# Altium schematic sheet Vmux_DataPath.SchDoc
size A3; DocumentNumber: 3; SheetNumber: 3; SheetTotal: 5
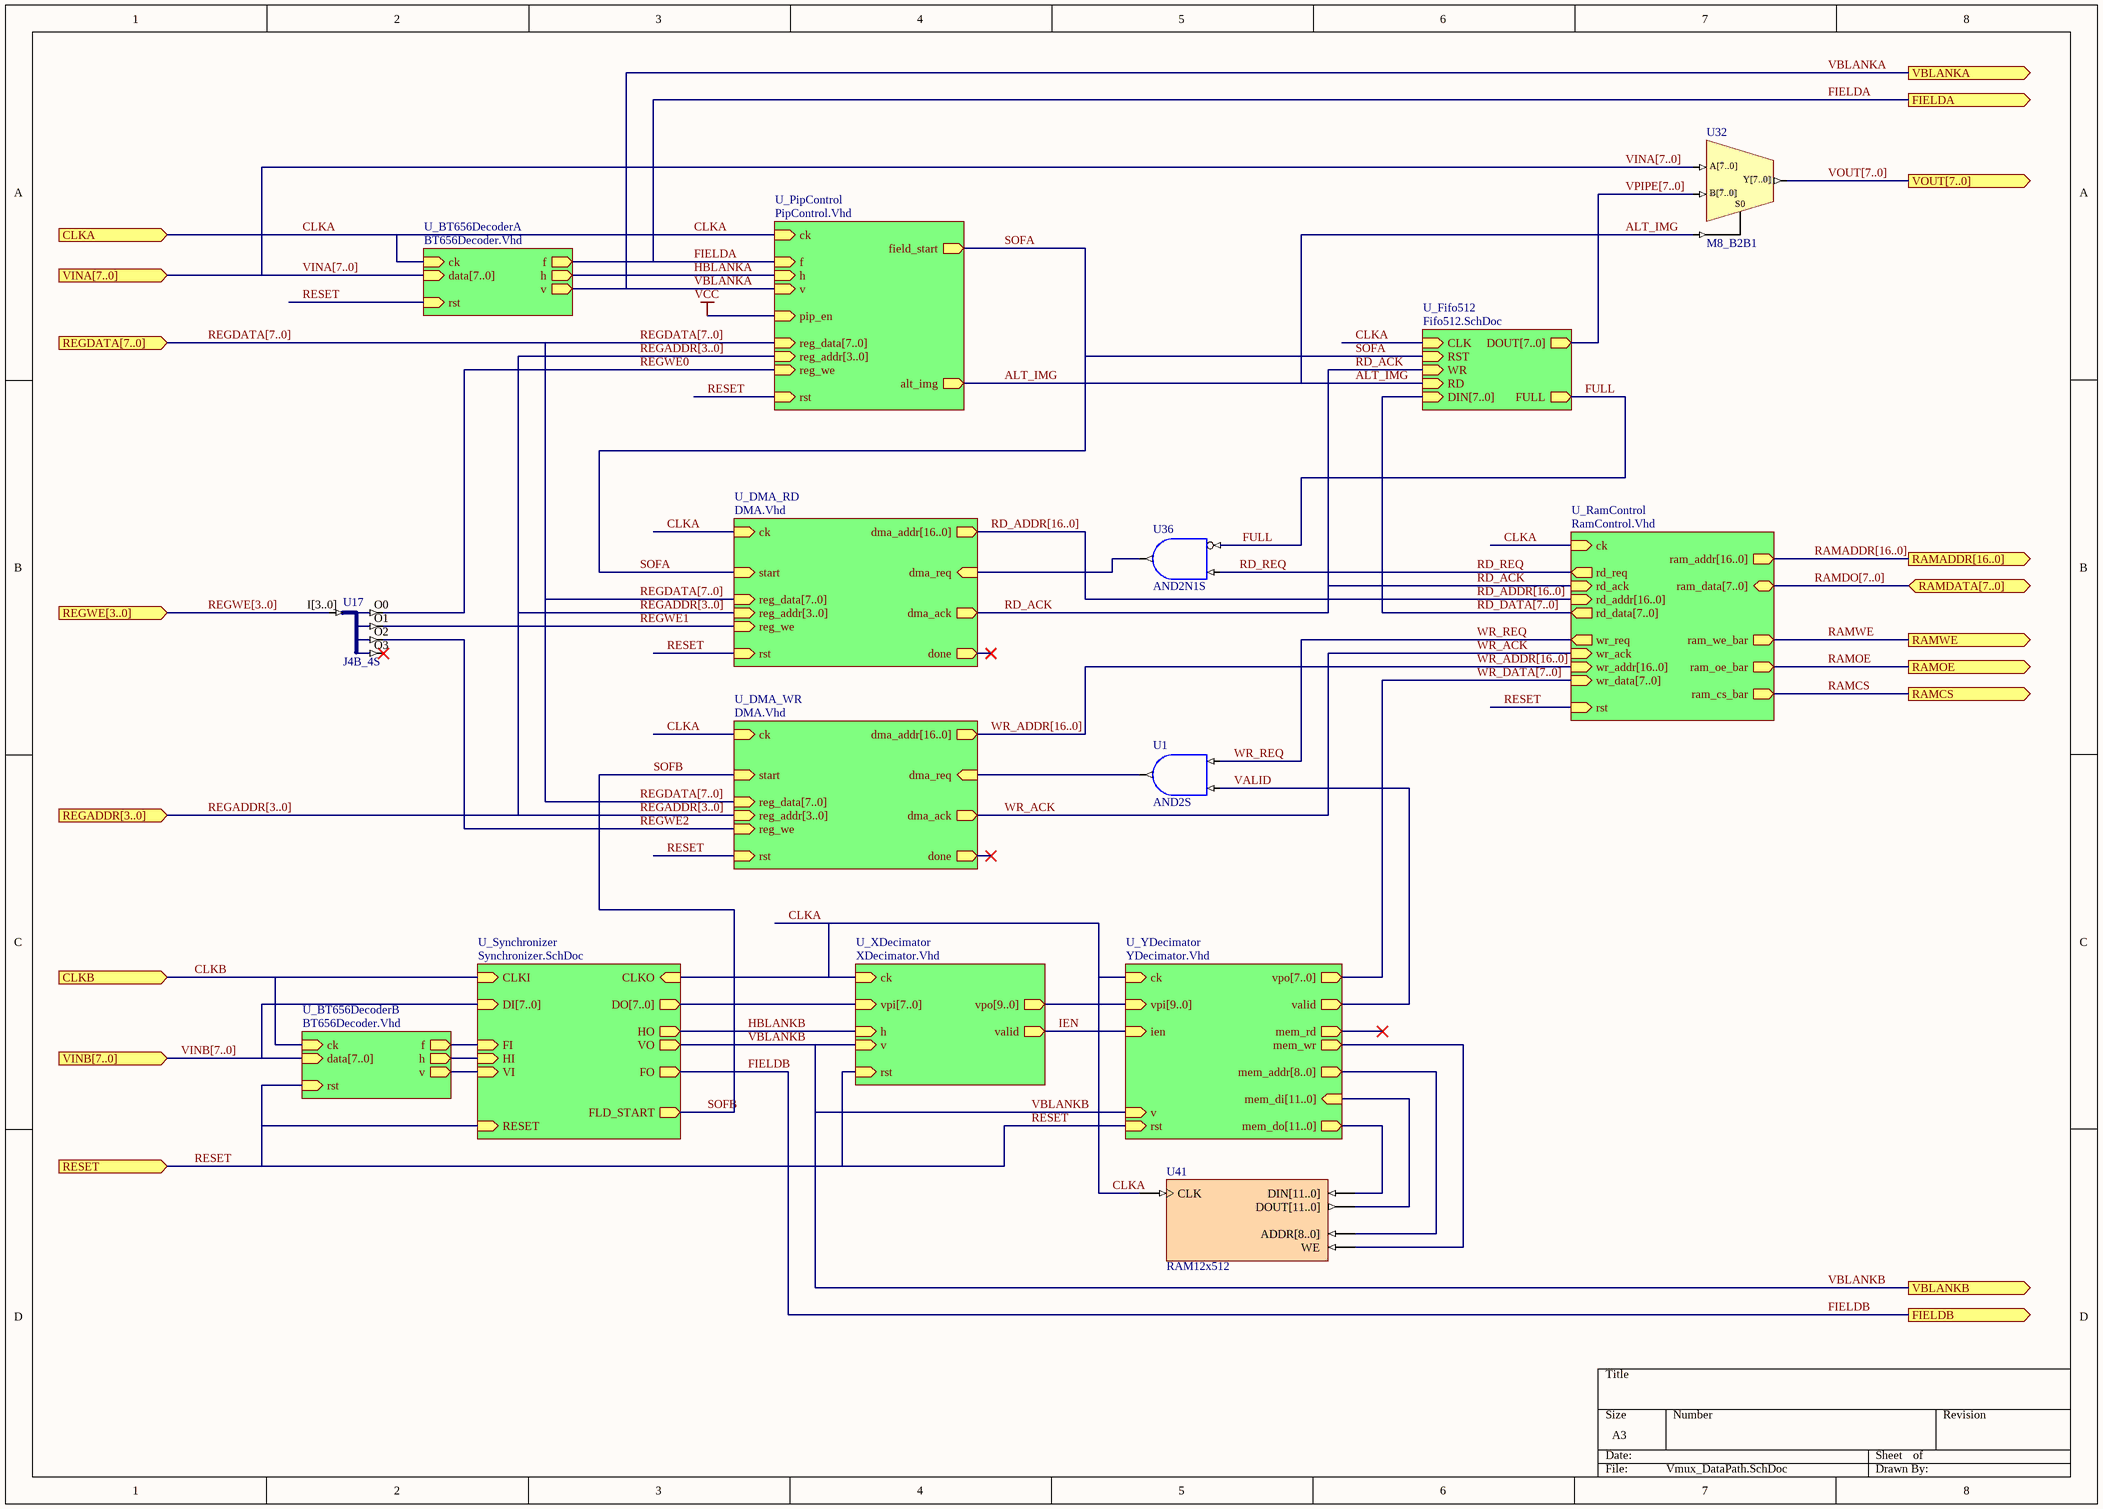
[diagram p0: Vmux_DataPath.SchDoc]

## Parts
U1  AND2S
U17  J4B_4S
U32  M8_B2B1
U36  AND2N1S
U41  RAM12x512

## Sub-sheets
U_BT656DecoderA = BT656Decoder.Vhd: ck (in), data[7..0] (in), f (out), h (out), rst (in), v (out)  | VHDLENTITY: BT656Decoder
U_BT656DecoderB = BT656Decoder.Vhd: ck (in), data[7..0] (in), f (out), h (out), rst (in), v (out)  | VHDLENTITY: BT656Decoder
U_DMA_RD = DMA.Vhd: ck (in), dma_ack (out), dma_addr[16..0] (out), dma_req (in), done (out), reg_addr[3..0] (in), reg_data[7..0] (in), reg_we (in), rst (in), start (in)  | VHDLENTITY: DMA
U_DMA_WR = DMA.Vhd: ck (in), dma_ack (out), dma_addr[16..0] (out), dma_req (in), done (out), reg_addr[3..0] (in), reg_data[7..0] (in), reg_we (in), rst (in), start (in)  | VHDLENTITY: DMA
U_Fifo512 = Fifo512.SchDoc: DOUT[7..0] (out), DIN[7..0] (in), CLK (in), RST (in), WR (in), RD (in), FULL (out)
U_PipControl = PipControl.Vhd: alt_img (out), ck (in), f (in), field_start (out), h (in), pip_en (in), reg_addr[3..0] (in), reg_data[7..0] (in), reg_we (in), rst (in), v (in)  | VHDLENTITY: PipControl
U_RamControl = RamControl.Vhd: ck (in), ram_addr[16..0] (out), ram_cs_bar (out), ram_data[7..0] (bidir), ram_oe_bar (out), ram_we_bar (out), rd_ack (in), rd_addr[16..0] (in), rd_data[7..0] (out), rd_req (out), rst (in), wr_ack (in), wr_addr[16..0] (in), wr_data[7..0] (in), wr_req (out)  | VHDLENTITY: RamControl
U_Synchronizer = Synchronizer.SchDoc: DI[7..0] (in), CLKI (in), HI (in), HO (out), DO[7..0] (out), CLKO (in), RESET (in), FI (in), VI (in), VO (out), FO (out), FLD_START (out)
U_XDecimator = XDecimator.Vhd: ck (in), h (in), rst (in), v (in), valid (out), vpi[7..0] (in), vpo[9..0] (out)  | VHDLENTITY: XDecimator
U_YDecimator = YDecimator.Vhd: ck (in), ien (in), mem_addr[8..0] (out), mem_di[11..0] (in), mem_do[11..0] (out), mem_rd (out), mem_wr (out), rst (in), v (in), valid (out), vpi[9..0] (in), vpo[7..0] (out)  | VHDLENTITY: YDecimator

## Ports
CLKA (in), CLKB (in), FIELDA (out), FIELDB (out), RAMADDR[16..0] (out), RAMCS (out), RAMDATA[7..0] (bidir), RAMOE (out), RAMWE (out), REGADDR[3..0] (in), REGDATA[7..0] (in), REGWE[3..0] (in), RESET (in), VBLANKA (out), VBLANKB (out), VINA[7..0] (in), VINB[7..0] (in), VOUT[7..0] (out)

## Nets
ALT_IMG: U32.S0 ; sheet U_Fifo512/RD, sheet U_PipControl/alt_img
CLKA: U41.CLK ; port CLKA, sheet U_Fifo512/CLK, sheet U_Synchronizer/CLKO, sheet U_PipControl/ck, sheet U_RamControl/ck, sheet U_XDecimator/ck, sheet U_BT656DecoderA/ck, sheet U_DMA_RD/ck, sheet U_DMA_WR/ck, sheet U_YDecimator/ck
CLKB: port CLKB, sheet U_Synchronizer/CLKI, sheet U_BT656DecoderB/ck
FIELDA: port FIELDA, sheet U_PipControl/f, sheet U_BT656DecoderA/f
FIELDB: port FIELDB, sheet U_Synchronizer/FO
FULL: U36.I0 ; sheet U_Fifo512/FULL
HBLANKA: sheet U_PipControl/h, sheet U_BT656DecoderA/h
HBLANKB: sheet U_Synchronizer/HO, sheet U_XDecimator/h
IEN: sheet U_XDecimator/valid, sheet U_YDecimator/ien
RAMCS: port RAMCS, sheet U_RamControl/ram_cs_bar
RAMOE: port RAMOE, sheet U_RamControl/ram_oe_bar
RAMWE: port RAMWE, sheet U_RamControl/ram_we_bar
RD_ACK: sheet U_Fifo512/WR, sheet U_RamControl/rd_ack, sheet U_DMA_RD/dma_ack
RD_REQ: U36.I1 ; sheet U_RamControl/rd_req
REGWE0: U17.O0 ; sheet U_PipControl/reg_we
REGWE1: U17.O1 ; sheet U_DMA_RD/reg_we
REGWE2: U17.O2 ; sheet U_DMA_WR/reg_we
RESET: port RESET, sheet U_Synchronizer/RESET, sheet U_PipControl/rst, sheet U_RamControl/rst, sheet U_XDecimator/rst, sheet U_BT656DecoderA/rst, sheet U_BT656DecoderB/rst, sheet U_DMA_RD/rst, sheet U_DMA_WR/rst, sheet U_YDecimator/rst
SOFA: sheet U_Fifo512/RST, sheet U_PipControl/field_start, sheet U_DMA_RD/start
SOFB: sheet U_Synchronizer/FLD_START, sheet U_DMA_WR/start
VALID: U1.I1 ; sheet U_YDecimator/valid
VBLANKA: port VBLANKA, sheet U_PipControl/v, sheet U_BT656DecoderA/v
VBLANKB: port VBLANKB, sheet U_Synchronizer/VO, sheet U_XDecimator/v, sheet U_YDecimator/v
WR_ACK: sheet U_RamControl/wr_ack, sheet U_DMA_WR/dma_ack
WR_REQ: U1.I0 ; sheet U_RamControl/wr_req
NetU1_O: U1.O ; sheet U_DMA_WR/dma_req
NetU36_O: U36.O ; sheet U_DMA_RD/dma_req
NetU41_WE: U41.WE ; sheet U_YDecimator/mem_wr
(unnamed): sheet U_Synchronizer/HI, sheet U_BT656DecoderB/h
(unnamed): sheet U_Synchronizer/FI, sheet U_BT656DecoderB/f  [a separate net that carries the same name]
(unnamed): sheet U_Synchronizer/VI, sheet U_BT656DecoderB/v  [a separate net that carries the same name]

Not connected (* = marked no-connect by the designer): U17 I[3..0] O3*; U32 A[7..0] B[7..0] Y[7..0]; U41 ADDR[8..0] DIN[11..0] DOUT[11..0]

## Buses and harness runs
bus RAMADDR[16..0] = port RAMADDR[16..0] = sheet U_RamControl/ram_addr[16..0]
bus RAMDO[7..0] = port RAMDATA[7..0] = sheet U_RamControl/ram_data[7..0]
bus RD_ADDR[16..0] = sheet U_DMA_RD/dma_addr[16..0] = sheet U_RamControl/rd_addr[16..0]
bus RD_DATA[7..0] = sheet U_Fifo512/DIN[7..0] = sheet U_RamControl/rd_data[7..0]
bus REGADDR[3..0] = port REGADDR[3..0] = sheet U_DMA_RD/reg_addr[3..0] = sheet U_DMA_WR/reg_addr[3..0] = sheet U_PipControl/reg_addr[3..0]
bus REGDATA[7..0] = port REGDATA[7..0] = sheet U_DMA_RD/reg_data[7..0] = sheet U_DMA_WR/reg_data[7..0] = sheet U_PipControl/reg_data[7..0]
bus REGWE[3..0] = port REGWE[3..0]
bus sheet U_Synchronizer/DO[7..0] = sheet U_XDecimator/vpi[7..0]
bus sheet U_XDecimator/vpo[9..0] = sheet U_YDecimator/vpi[9..0]
bus VINA[7..0] = port VINA[7..0] = sheet U_BT656DecoderA/data[7..0]
bus VINB[7..0] = port VINB[7..0] = sheet U_BT656DecoderB/data[7..0] = sheet U_Synchronizer/DI[7..0]
bus VOUT[7..0] = port VOUT[7..0]
bus VPIPE[7..0] = sheet U_Fifo512/DOUT[7..0]
bus WR_ADDR[16..0] = sheet U_DMA_WR/dma_addr[16..0] = sheet U_RamControl/wr_addr[16..0]
bus WR_DATA[7..0] = sheet U_RamControl/wr_data[7..0] = sheet U_YDecimator/vpo[7..0]

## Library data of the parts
U1 = AND2S: 2-Input AND Gate, Single Pin Version; Xilinx Equivalent: AND2; ArchiveName: GENERIC
U17 = J4B_4S: 4-Bit input bus to 4 Single pin outputs; ArchiveName: GENERIC
U32 = M8_B2B1: 2x8-Bit Bus to 1x8-Bit Bus Multiplexer; ArchiveName: GENERIC
U36 = AND2N1S: 2-Input AND Gate with Active Low A Input, Single Pin Version; Xilinx Equivalent: AND2B1; ArchiveName: GENERIC
U41 = RAM12x512: Single Port Random Access Memory 512 x 12; Memory_Depth: 512; Memory_Type: RAM_SinglePortBlock; Memory_Width: 12; Memory_ClockEdge: Rising; Nexus_Core: Memory_Program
